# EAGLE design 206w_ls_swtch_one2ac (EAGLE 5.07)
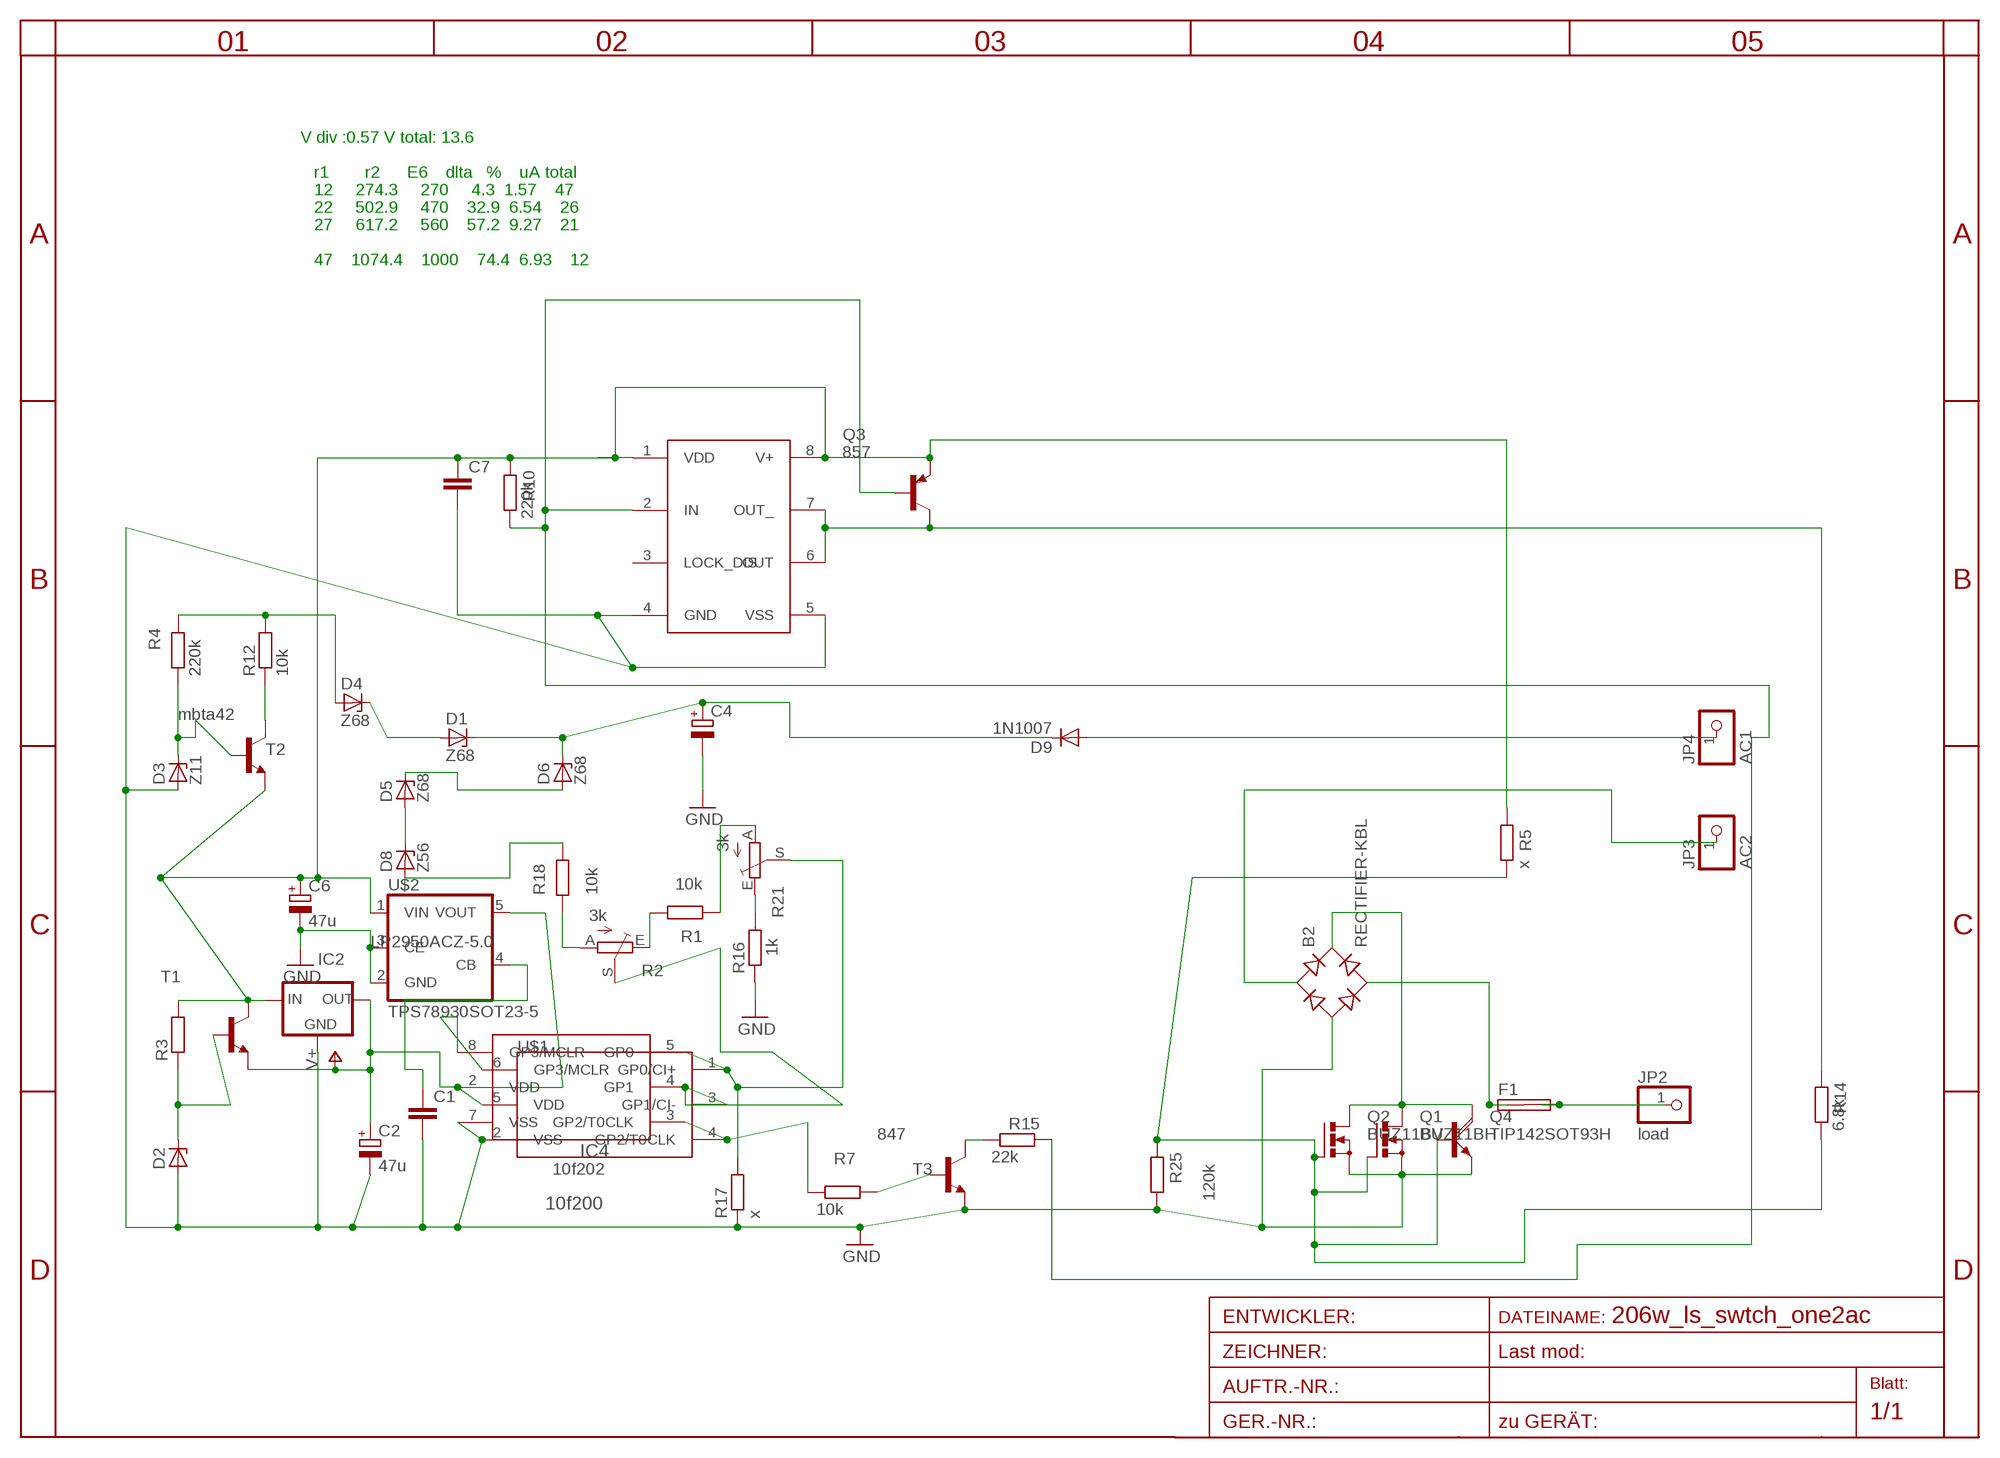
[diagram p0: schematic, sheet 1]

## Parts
B2  RECTIFIER-KBL  [KBL]
C1  C-EUC0805  [C0805]
C2  47u  CPOL-EUSANYO_SMD_C6  [SANYO-OSCON_SMD_C6]
C4  CPOL-EUE5-8.5  [E5-8,5]
C6  47u  CPOL-EUSANYO_SMD_E12  [SANYO-OSCON_SMD_E12]
C7  C-EUC1206  [C1206]
D1  Z68  ZENER-DIODESOD80C  [SOD80C]
D2  ZENER-DIODESOD80C  [SOD80C]
D3  Z11  ZENER-DIODESOD80C  [SOD80C]
D4  Z68  ZENER-DIODESOD80C  [SOD80C]
D5  Z68  ZENER-DIODESOD80C  [SOD80C]
D6  Z68  ZENER-DIODESOD80C  [SOD80C]
D8  Z56  ZENER-DIODESOD80C  [SOD80C]
D9  1N1007  DIODE-SOD80C  [SOD80C]
F1  SHK20L7MM5  [7MM5]
IC2  LP2950ACZ-5.0  [TO92]
IC3  TC4432X  [SO-08]
IC4  10f200  PIC10F200P  [DIL8]
JP2  load  PINHD-1X11MM6  [1X1MM8]
JP3  AC2  PINHD-1X11MM6  [1X1MM8]
JP4  AC1  PINHD-1X11MM6  [1X1MM8]
Q1  BUZ11BH  [TO220BH]
Q2  BUZ11BV  [TO220BV]
Q3  857  BC857BSMD  [SOT23-BEC]
Q4  TIP142SOT93H  [SOT93]
R1  10k  R-EU_R1206  [R1206]
R2  3k  TRIM_EU-CA6V  [CA6V]
R3  R-EU_R1206  [R1206]
R4  220k  R-EU_R1206  [R1206]
R5  x  R-EU_R0805  [R0805]
R7  10k  R-EU_R0805  [R0805]
R10  220k  R-EU_R0805  [R0805]
R12  10k  R-EU_R1206  [R1206]
R14  6.8k  R-EU_R0805  [R0805]
R15  22k  R-EU_R0805  [R0805]
R16  1k  R-EU_R0805  [R0805]
R17  x  R-EU_R0805  [R0805]
R18  10k  R-EU_R1206  [R1206]
R21  3k  TRIM_EU-CA6V  [CA6V]
R25  120k  R-EU_R0805  [R0805]
T1  BC846BLT1-NPN-SOT23-BEC  [SOT23-BEC]
T2  mbta42  BC846BLT1-NPN-SOT23-BEC  [SOT23-BEC]
T3  847  BC846BLT1-NPN-SOT23-BEC  [SOT23-BEC]
U$1  10f202  PIC10F202OT  [SOT23-6]
U$2  TPS78930SOT23-5  [SOT25]

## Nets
BB: IC3.2(IN) Q3.B R10.1 R15.2
D: B2.AC2 F1.1A F1.1B
DRAIN: B2.+ Q1.D Q2.D Q4.C
GND: B2.- C1.2 C2.- C4.- C6.- C7.2 D2.A D3.A IC2.2(GND) IC3.4(GND) IC3.5(VSS) IC4.7(VSS) Q1.S Q2.S Q4.E R16.1 R17.1 R25.1 T3.E U$1.2(VSS) U$2.2(GND) U$2.3(CE)
IN+: D9.A JP4.1
N$1: IC4.5(GP0) R17.2 R21.S U$1.1(GP0/CI+)
N$2: IC4.8(GP3/MCLR) U$1.6(GP3/MCLR)
N$3: Q1.G Q2.G Q4.B R5.1 R14.1 R25.2
N$4: IC4.4(GP1) R2.S U$1.3(GP1/CI-)
N$5: R16.2 R21.E
N$6: D2.C R3.1 T1.B
N$7: B2.AC1 JP3.1
N$8: R1.1 R21.A
N$9: IC4.3(GP2/T0CLK) R7.1 U$1.4(GP2/T0CLK)
N$10: D5.C D6.A
N$11: IC3.6(OUT) IC3.7(OUT_) Q3.C R14.2
N$12: D3.C R4.1 T2.B
N$13: R1.2 R2.E
N$14: R2.A R18.1
N$16: R12.1 T2.C
N$17: D5.A D8.C
N$18: D1.A D4.C
N$19: D8.A R18.2
N$21: D4.A R4.2 R12.2
N$22: C1.1 U$2.4(CB)
N$26: R7.2 T3.B
N$31: R15.1 T3.C
OUT-: F1.2A F1.2B JP2.1
V60: C4.+ D1.C D6.C D9.C
V+: C2.+ IC2.1(OUT) IC4.2(VDD) T1.E U$1.5(VDD) U$2.5(VOUT)
VCC: C6.+ C7.1 IC2.3(IN) IC3.1(VDD) IC3.8(V+) Q3.E R3.2 R5.2 R10.2 T1.C T2.E U$2.1(VIN)
Unconnected: IC3.3(LOCK_DIS)

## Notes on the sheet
- V div :0.57 V total: 13.6
- r1        r2      E6    dlta   %    uA total
- 12     274.3     270     4.3  1.57    47
- 22     502.9     470    32.9  6.54    26
- 27     617.2     560    57.2  9.27    21
- 47    1074.4    1000    74.4  6.93    12

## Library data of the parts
B2 = rectifier:RECTIFIER-: Rectifier
C1 C7 = rcl:C-EU: CAPACITOR, European symbol
C2 C4 C6 = rcl:CPOL-EU: POLARIZED CAPACITOR, European symbol
D1-D6 D8 = diode-1:ZENER-DIODE: Z-Diode
D9 = diode:DIODE-: DIODE
F1 = fuse:SHK20L: FUSE HOLDER 5 x 20 mm, SH contact, SHH1 Schukat, E1073 Buerklin
IC2 = v-reg:LP2950?*: Source: http://cache.national.com/ds/LP/LP2950.pdf
IC3 = microchip:TC4432
IC4 = microchip-5:PIC10F20*: uPC nW 0,25/0,5k Program Flash memory
JP2-JP4 = pinhead:PINHD-1X1: PIN HEADER
Q1 Q2 = transistor-power:BUZ11: N-CHANNEL MOS FET
Q3 = transistor-pnp:BC857*: PNP Transistror
Q4 = transistor-power:TIP142: NPN DARLINGTON TRANSISTOR
R1 R7 R17 R18 = rcl-2:R-EU_: RESISTOR, European symbol
R2 R21 = pot:TRIM_EU-: POTENTIOMETER
R3-R5 R10 R12 R14-R16 R25 = rcl:R-EU_: RESISTOR, European symbol
T1-T3 = transistor-neu-to92:*-NPN-: NPN Transistror
U$1 = microchip-5:PIC10F2*: uPC nW 0,25/0,5k Program Flash memory Comparator
U$2 = v-reg:TPS78930

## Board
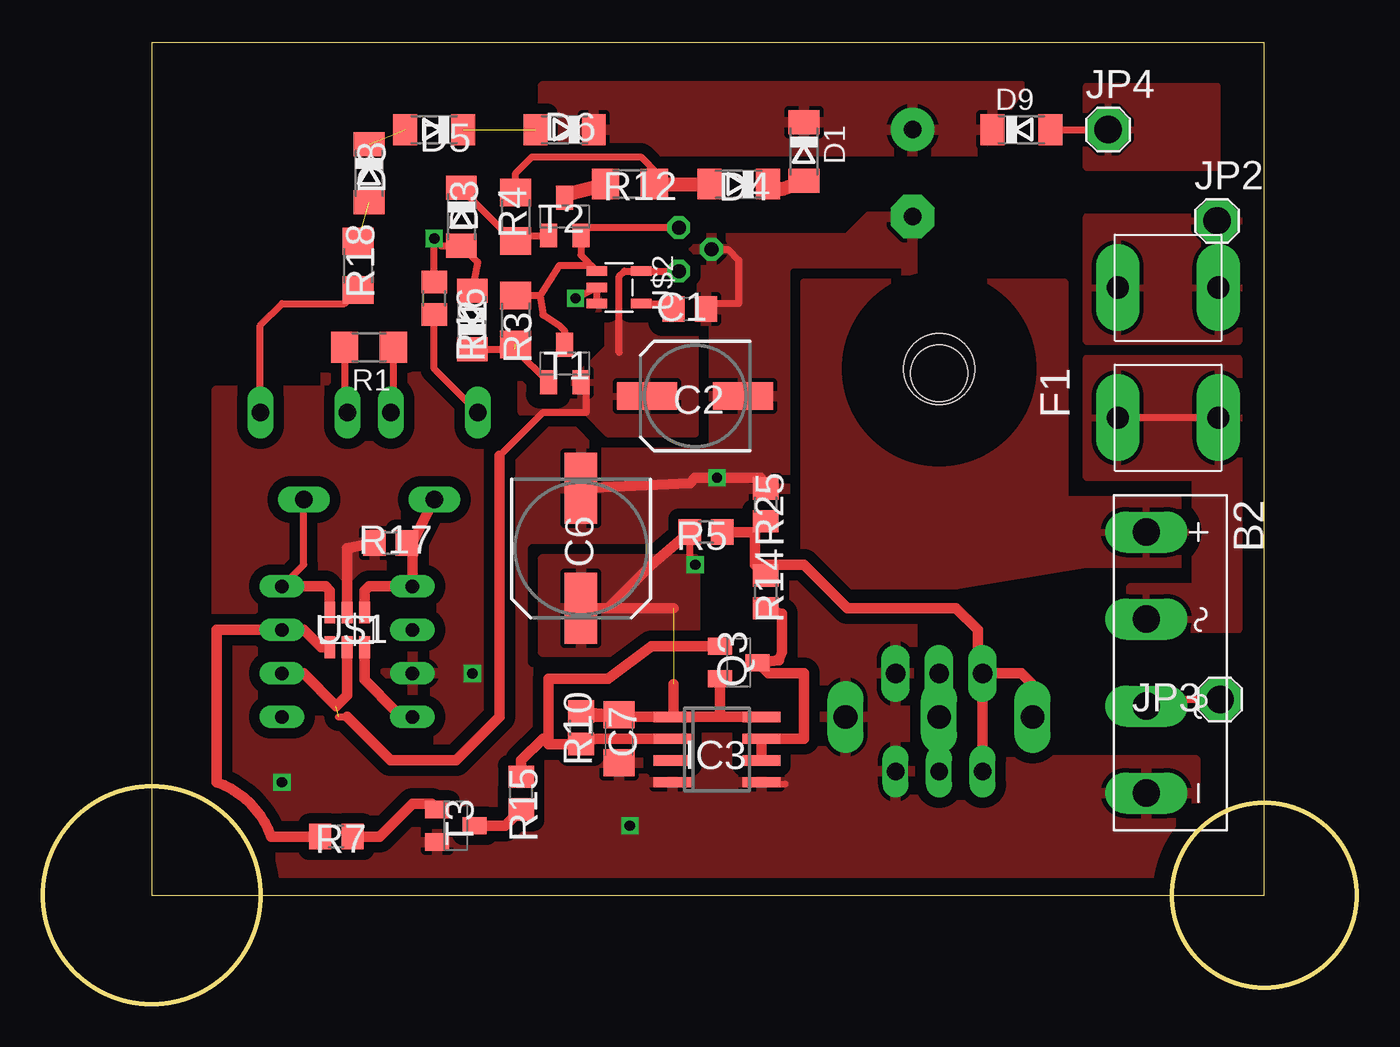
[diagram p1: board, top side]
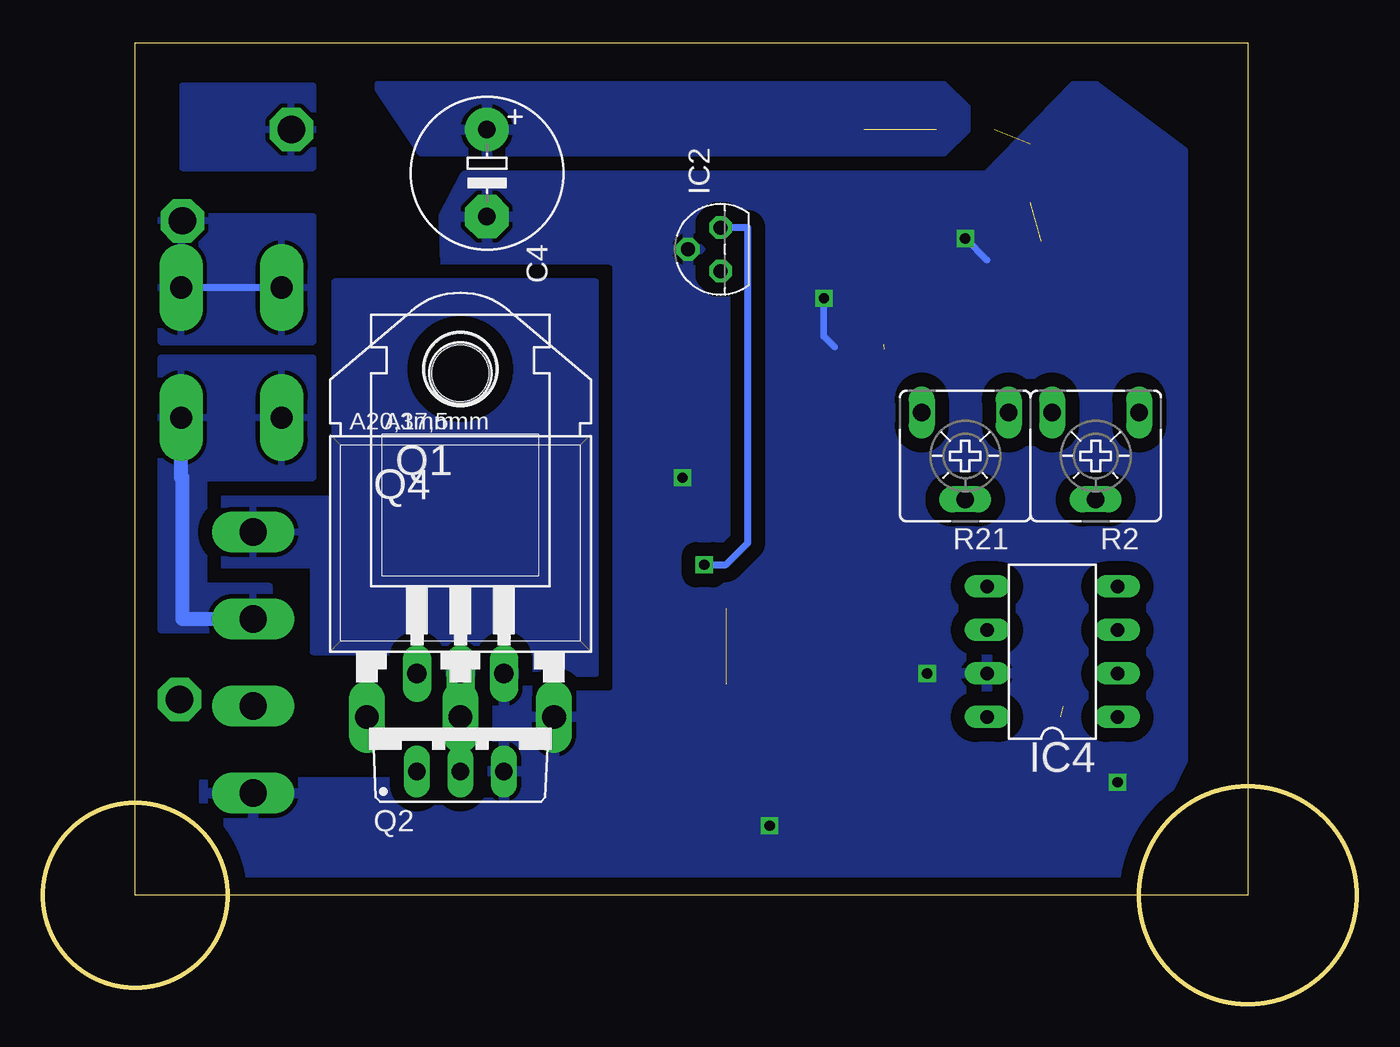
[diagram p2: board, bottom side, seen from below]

Size 76.74 x 56.11 mm. Coordinates in mm from the lower left corner, seen from the top.
Outline: 6.35,6.35 71.35,6.35 71.35,56.11 6.35,56.11 6.35,6.35
Outline: circle at 71.35,6.35 radius 5.39
Outline: circle at 6.35,6.35 radius 6.35
Copper layers (1*16): Top 0.035mm / dielectric 1.5mm / Bottom 0.035mm
Design rules "default": minimum track width 10mil, minimum drill 24mil, track to track 8mil, track to pad 8mil, pad to pad 8mil, via to via 8mil, smd to smd 8mil, copper to edge 40mil, drill to drill 8mil, minimum pad ring 10mil, minimum via ring 8mil, stop-mask expansion 4mil, vias tented up to drill 0mil, thermal gap 10mil

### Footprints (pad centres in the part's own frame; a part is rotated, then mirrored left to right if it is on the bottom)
KBL = drill 1.6 long: + -7.62,-1.27; - 7.62,-1.27; AC1 2.54,-1.27; AC2 -2.54,-1.27
C0805 = smd 1.3 x 1.5: 1 -0.95,0; 2 0.95,0
SANYO-OSCON_SMD_C6 = smd 3.5 x 1.6: + 2.8,0; - -2.8,0
E5-8,5 = drill 1.016 pad 2.54 round: + -2.54,0 | drill 1.016 pad 2.54 octagon: - 2.54,0
SANYO-OSCON_SMD_E12 = smd 4.15 x 1.9: + 3.5,0; - -3.5,0
C1206 = smd 1.6 x 1.8: 1 -1.4,0; 2 1.4,0
SOD80C = smd 1.4 x 1.8: A 1.7,0; C -1.7,0
7MM5 = drill 1.3 pad 2.54 long: 1A -3.8,2.94; 1B -3.8,-2.94; 2A 3.8,2.94; 2B 3.8,-2.94
TO92 = drill 0.813 octagon: 1 -1.27,0; 2 0,1.905; 3 1.27,0
SO-08 = smd 0.6 x 2.2: 1 -1.905,-2.6; 2 -0.635,-2.6; 3 0.635,-2.6; 4 1.905,-2.6; 5 1.905,2.6; 6 0.635,2.6; 7 -0.635,2.6; 8 -1.905,2.6
DIL8 = drill 0.8 long: 1 -3.81,-3.81; 2 -1.27,-3.81; 3 1.27,-3.81; 4 3.81,-3.81; 5 3.81,3.81; 6 1.27,3.81; 7 -1.27,3.81; 8 -3.81,3.81
1X1MM8 = drill 1.6 pad 2.54 octagon: 1 0,0
TO220BH = drill 1.118 long: D 0,-6.35; G -2.54,-6.35; S 2.54,-6.35 | hole 3.302: 0,11.176
TO220BV = drill 1.016 long: D 0,-2.54; G -2.54,-2.54; S 2.54,-2.54
SOT23-BEC = smd 1 x 1.4: B -0.95,-1.1; C 0,1.1; E 0.95,-1.1
SOT93 = drill 1.397 long: B -5.461,-10.16; C 0,-10.16; E 5.461,-10.16 | hole 4.115: 0,10.16
R1206 = smd 1.6 x 1.803: 1 -1.422,0; 2 1.422,0
CA6V = drill 1.016 long: A -2.54,-2.54; E 2.54,-2.54; S 0,2.54
R0805 = smd 1.3 x 1.5: 1 -0.95,0; 2 0.95,0
SOT23-6 = smd 0.635 x 1.27: 1 -1.016,-1.016; 2 0,-1.016; 3 1.016,-1.016; 4 1.016,1.016; 5 0,1.016; 6 -1.016,1.016
SOT25 = smd 0.55 x 1.2: 1 -0.95,-1.3; 2 0,-1.3; 3 0.95,-1.3; 4 0.95,1.3; 5 -0.95,1.3

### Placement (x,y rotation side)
B2  65.72,19.92 270 top
C1  37.78,40.56 0 top
C2  38.1,35.48 180 top
C4  50.8,48.5 270 bottom
C6  31.43,26.59 270 top
C7  33.66,15.48 270 top
D1  44.45,49.77 270 top
D2  25.08,39.93 90 top
D3  24.45,45.96 270 top
D4  40.64,47.87 180 top
D5  22.86,51.04 180 top
D6  30.48,51.04 180 top
D8  19.05,48.5 270 top
D9  57.15,51.04 0 top
F1  65.72,38.02 90 top
IC2  37.15,44.05 90 bottom
IC3  39.37,14.85 270 top
IC4  17.78,20.56 90 bottom
JP2  68.59,45.72 0 top
JP3  68.75,17.78 0 top
JP4  62.23,51.04 0 top
Q1  52.35,25.64 0 bottom
Q2  52.35,16.12 0 bottom
Q3  40.64,19.92 270 top
Q4  52.35,26.91 0 bottom
R1  19.05,38.34 180 top
R2  15.24,31.99 180 bottom
R3  27.62,39.93 90 top
R4  27.62,45.96 90 top
R5  38.73,27.55 180 top
R7  17.14,9.76 0 top
R10  31.43,16.12 90 top
R12  34.29,47.87 0 top
R14  42.23,24.05 270 top
R15  27.94,12.3 90 top
R16  22.86,41.2 270 top
R17  20.32,26.91 0 top
R18  18.41,43.1 90 top
R21  22.86,31.99 180 bottom
R25  42.23,29.13 270 top
T1  30.48,37.39 0 top
T2  30.48,45.96 0 top
T3  24.13,10.4 270 top
U$1  17.78,21.83 180 top
U$2  33.66,41.83 270 top

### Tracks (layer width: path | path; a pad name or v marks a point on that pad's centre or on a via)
BB
  Top 0.61: Q3.B 35.56,20.88 33.02,18.97 29.53,18.97 29.53,15.48 | 29.53,15.48 29.53,15.16 R10.1 32.38,15.48 IC3.2 | R15.2 27.94,14.21 29.21,15.48 29.53,15.48
D
  Top 0.406: F1.1B F1.1A
  Bottom 0.813: B2.AC2 68.58,22.46 68.58,30.72 68.66,30.72 F1.1B
  pour Bottom (isolate 0.813): 60.96,37.7 69.85,37.7 69.85,21.83 63.5,21.83 63.5,24.37 67.31,24.37 67.31,30.72 60.96,30.72
  pour Top (isolate 0.813): 60.96,37.7 69.85,37.7 69.85,21.83 63.5,21.83 63.5,24.37 67.31,24.37 67.31,30.72 60.96,30.72
DRAIN
  Top 1.016: Q2.D Q4.C Q1.D
  pour Top (isolate 0.61, rank 2): 44.45,42.15 59.69,42.15 59.69,29.45 67.31,29.45 67.31,25.64 60.96,25.64 53.34,24.37 44.45,24.37
  pour Bottom (isolate 0.813, rank 2): 44.45,42.15 59.69,42.15 59.69,29.45 67.31,29.45 67.31,25.64 60.96,25.64 60.96,20.56 53.34,20.56 53.34,19.29 44.45,19.29
GND  (via drill 0.6)
  Top 0.406: IC3.5 43.35,12.83 | D2.A 25.4,43.31 D3.A 23.29,44.26 v22.86,44.69 R16.1 | v31.12,41.2 U$2.2 U$2.3 | IC2.2 40.01,44.05 40.64,43.42 40.64,40.88 39.05,40.88 C1.2
  Top 0.61: C6.- 37.79,30.41 38.1,30.72 41.91,30.72 | U$1.2 17.78,26.59 R17.1
  Bottom 0.406: v31.12,41.2 31.12,38.98 30.48,38.34 | v22.86,44.69 21.59,43.42
  other vias: 34.29,10.4 39.37,30.72 13.97,12.94 25.08,19.29
  pour Top (isolate 0.61, rank 3): 26.67,38.34 16.51,39.61 16.51,35.8 10.16,35.8 10.16,12.94 13.97,6.35 67.31,6.35 67.31,14.21 50.8,14.21 50.8,45.96 48.26,45.96 46.99,44.69 34.29,44.69 31.75,38.34
  pour Bottom (isolate 0.813, rank 3): 16.51,53.58 15.24,53.58 10.16,49.77 10.16,14.21 13.97,6.35 67.31,7.62 67.31,12.94 52.07,12.94 52.07,16.75 53.34,45.96 52.07,48.35 21.59,48.35
IN+
  Top 0.406: D9.A JP4.1
  pour Top (isolate 0.813): 60.96,53.58 68.58,53.58 68.58,48.82 60.96,48.82
  pour Bottom (isolate 0.813): 60.96,53.58 68.58,53.58 68.58,48.82 60.96,48.82
N$1
  Top 0.61: U$1.1 18.8,24.12 19.05,24.37 IC4.5 21.59,26.91 | 21.59,26.91 R21.S | 21.59,26.91 R17.2
N$2
  Top 0.61: U$1.6 18.8,18.91 20.64,17.07 21.27,17.07 IC4.8
N$3
  Top 0.406: 54.61,19.57 Q1.G | 58.42,18.02 58.42,17.36 Q4.B | R25.2 41.91,28.18 41.59,27.55
  Top 0.61: Q2.G Q1.G 57.15,19.29 58.42,18.02 | R5.1 41.59,27.55 41.59,25.64 42.54,25.64 | 42.54,25.64 R14.1 | 42.54,25.64 44.45,25.64 46.99,23.1 53.34,23.1 54.61,21.83 54.61,19.57
N$4
  Top 0.406: R2.S 15.24,25.64 IC4.4
  Top 0.61: U$1.3 16.76,24.12 16.51,24.37 IC4.4
N$5
  Top 0.406: R16.2 22.86,37.07 R21.E
N$6  (1 unrouted)
  Top 0.406: D2.C 27.59,38.23 T1.B
N$7
  Top 0.406: JP3.1 64.85,17.78 B2.AC1
N$8
  Top 0.406: R1.1 20.47,34.68 R21.A
N$9
  Top 0.61: U$1.4 16.26,20.81 15.24,21.83 IC4.3 10.16,21.83 10.16,12.94 arc-51 13.34,9.76 R7.1
N$10  (1 unrouted)
N$11
  Top 0.61: IC3.6 IC3.7 44.45,15.48 44.45,19.29 42.38,19.29 Q3.C 43.01,20.07 43.18,20.56 43.18,22.78 R14.2
N$12
  Top 0.406: T2.B 27.95,44.86 R4.1 27.15,45.01 26.99,45.01 24.45,47.55 D3.C
N$13
  Top 0.406: R1.2 17.63,34.68 R2.E
N$14
  Top 0.406: R2.A 12.7,39.61 13.97,40.88 17.61,40.88 R18.1
N$16
  Top 0.813: R12.1 30.48,47.23 T2.C
N$17  (1 unrouted)
N$18
  Top 0.61: D4.C 43.13,47.57
  Top 0.813: 43.13,47.57 D1.A
N$19  (1 unrouted)
N$21
  Top 0.406: R4.2 27.62,48.5 28.58,49.45 34.92,49.45 35.88,48.5 35.88,48.03 R12.2
  Top 0.813: R12.2 D4.A
N$22
  Top 0.406: U$2.4 36.51,40.88 C1.1
N$26
  Top 0.406: 22.71,11.67 T3.B
  Top 0.61: R7.2 19.69,9.76 21.59,11.67 22.71,11.67
N$31
  Top 0.61: T3.C 26.98,10.4 R15.1
OUT-
  Top 0.406: F1.2B 68.66,45.88 68.59,45.95 | 68.59,45.95 JP2.1 | 68.59,45.95 68.58,45.96
  Bottom 0.406: F1.2A F1.2B
  pour Top: 60.96,45.96 69.85,45.96 69.85,38.66 60.96,38.66
  pour Bottom: 60.96,45.96 69.85,45.96 69.85,38.66 60.96,38.66
V60
  pour Top (isolate 0.61): 57.15,53.58 29.21,53.58 29.21,49.77 54.61,49.77
  pour Bottom (isolate 0.61): 57.15,53.58 24.13,53.58 22.86,52.31 22.86,51.04 24.13,49.77 54.61,49.77
V+  (1 unrouted)
  Top 0.406: 17.27,16.75 17.78,16.75 | 33.66,38.02 33.66,42.47 33.97,42.78 U$2.5 IC2.1 | 26.67,31.99 29.21,34.53 31.75,34.53 31.75,35.97 T1.E
  Top 0.61: 26.67,31.99 26.67,16.75 24.13,14.21 20.32,14.21 17.78,16.75 | IC4.2 15.24,19.29 17.14,17.38 17.78,18.02 U$1.5
  pour Top (isolate 0.813): 36.83,40.88 38.1,40.88 38.1,33.26 33.02,33.26 31.75,34.53 27.94,34.53 27.94,37.07 31.75,37.07 33.02,38.34 33.02,40.88
VCC  (via drill 0.6)  (1 unrouted)
  Top 0.406: IC2.3 31.9,45.33 T2.E 31.43,43.71 U$2.1 32.03,43.1 30.16,43.1 29.05,41.35 | 29.05,41.35 R3.2 | T1.C 30.48,39.29 30.16,39.61 29.21,40.23 29.05,41.35 | R5.2 37.78,25.95 v38.1,25.64
  Top 0.61: Q3.E 39.54,16.9 39.69,16.75 | 41.27,16.75 IC3.8 39.69,16.75 | IC3.1 39.69,16.75 | IC3.1 31.88,16.75 C7.1 33.2,16.88 R10.2 | IC3.1 36.83,16.75 36.83,18.66 | R5.2 35.56,25.64 33.02,23.1 | 32.06,23.1 C6.+ 31.75,23.1 32.06,23.1 | 33.02,23.1 36.83,23.1 | 32.06,23.1 33.02,23.1
  Bottom 0.406: v38.1,25.64 36.83,25.64 35.56,26.91 35.56,45.33 IC2.3
  pour Top (isolate 0.61): 29.21,25.96 38.1,25.96 38.1,21.83 34.29,20.56 29.21,20.56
